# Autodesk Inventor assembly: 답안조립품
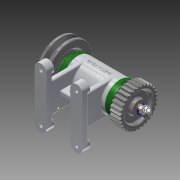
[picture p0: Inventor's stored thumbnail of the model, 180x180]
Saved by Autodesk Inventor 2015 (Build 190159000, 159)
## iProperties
Created: 2015-11
Part Number: 답안조립품
Document SubType Name: Assembly
Designer: Administrator
Author: Administrator
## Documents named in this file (14)
- C:\Users\Administrator\Desktop\451110V1037\답안조립품.iam
- C:\Users\Administrator\Desktop\451110V1037\본체.ipt
- C:\Users\Administrator\Desktop\451110V1037\축.ipt
- C:\Users\Administrator\Desktop\451110V1037\베어링 15 x 32 x 9.ipt
- C:\Users\Administrator\Desktop\451110V1037\커버.ipt
- C:\Users\Administrator\Desktop\451110V1037\볼트 M4 x 12.ipt
- C:\Users\Administrator\Desktop\451110V1037\오일 실 15 25 7.ipt
- C:\Users\Administrator\Desktop\451110V1037\키 3 x 3 x 12.ipt
- C:\Users\Administrator\Desktop\451110V1037\스프링와셔 8.ipt
- C:\Users\Administrator\Desktop\451110V1037\와셔 8x17.ipt
- C:\Users\Administrator\Desktop\451110V1037\V벨트풀리.ipt
- C:\Users\Administrator\Desktop\451110V1037\너트 M 8.ipt
- C:\Users\Administrator\Desktop\451110V1037\스퍼기어.ipt
- C:\Users\Administrator\Desktop\451110V1037\와셔 6x11.5.ipt
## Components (12 placed, 3 different names)
1. KS B 2023 6002 - 15 x 32 x 9:1
2. KS B 2023 6002 - 15 x 32 x 9:2
3. ISO 4762 M4 x 12:5
4. V벨트풀리:1
5. ISO 4762 M4 x 12:1
6. ISO 4762 M4 x 12:2
7. ISO 4762 M4 x 12:3
8. ISO 4762 M4 x 12:4
9. ISO 4762 M4 x 12:6
10. ISO 4762 M4 x 12:7
11. ISO 4762 M4 x 12:8
12. ISO 4762 M4 x 12:9
